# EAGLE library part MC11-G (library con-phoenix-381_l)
Mini-Combicon 3.81mm horizontal 11-polig (mit Gegenstecker)
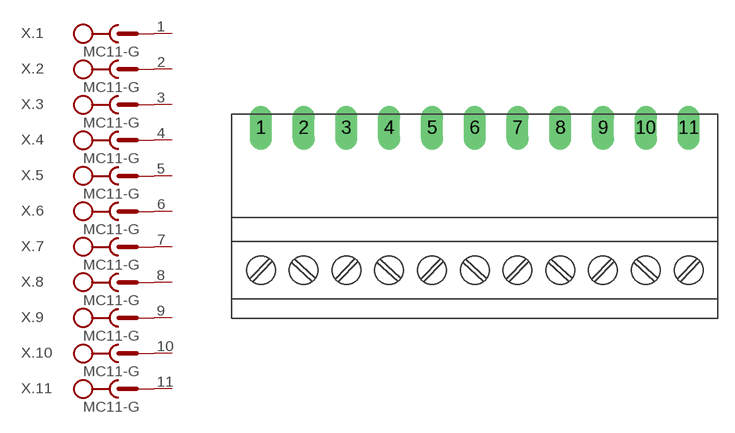
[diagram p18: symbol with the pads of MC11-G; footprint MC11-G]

Designator prefix X; gates .1=SK+V .2=SK+V .3=SK+V .4=SK+V .5=SK+V .6=SK+V .7=SK+V .8=SK+V .9=SK+V .10=SK+V .11=SK+V

## MC11-G  [MC11-G]
1  .1:SK  pas
2  .2:SK  pas
3  .3:SK  pas
4  .4:SK  pas
5  .5:SK  pas
6  .6:SK  pas
7  .7:SK  pas
8  .8:SK  pas
9  .9:SK  pas
10  .10:SK  pas
11  .11:SK  pas

## Footprint MC11-G (pad centres in mm)
Mini-Combicon 3.81mm horizontal 10-polig (mit Gegenstecker)
drill 1.3 long: 1 -19.05,0; 2 -15.24,0; 3 -11.43,0; 4 -7.62,0; 5 -3.81,0; 6 0,0; 7 3.81,0; 8 7.62,0; 9 11.43,0; 10 15.24,0; 11 19.05,0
